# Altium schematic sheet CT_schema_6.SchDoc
size 260 x 245 mm
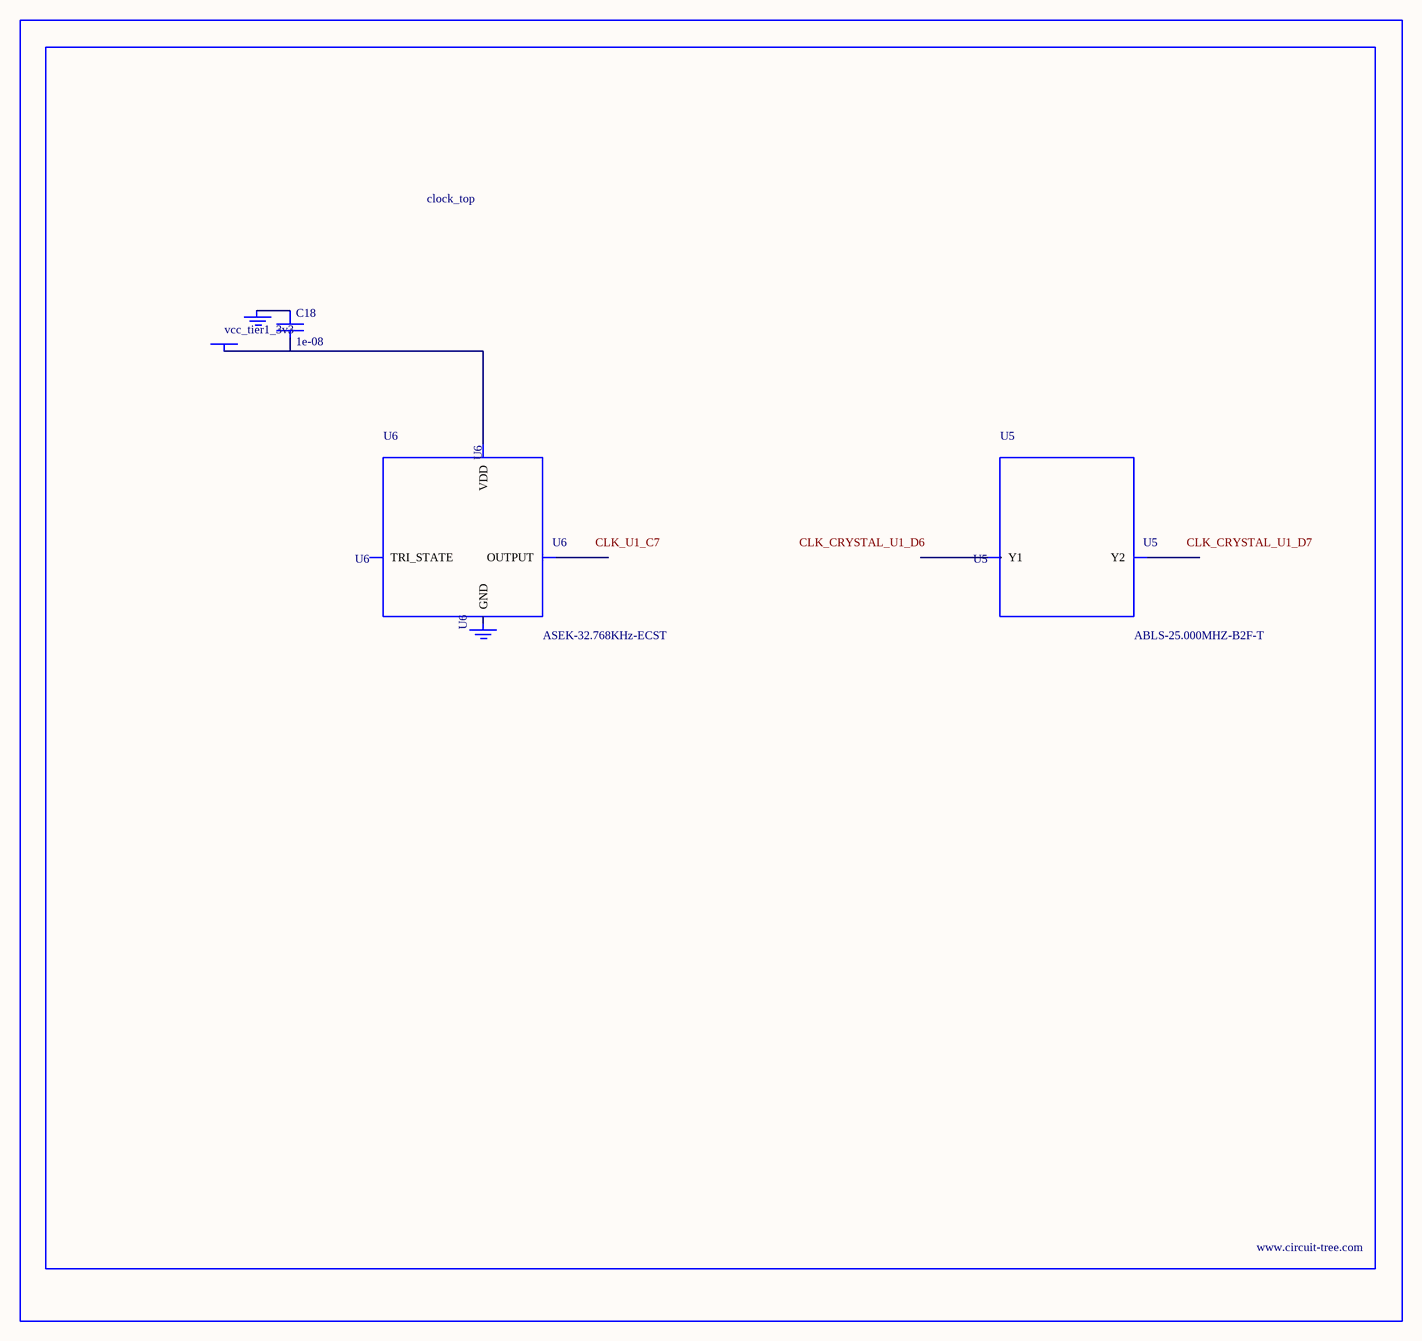
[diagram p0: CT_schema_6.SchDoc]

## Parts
BORDER5  (no value)
C18  1e-08  [C0402]
GND_INSTANCE_5_0  (no value)
GND_INSTANCE_5_1  (no value)
POWER_INSTANCE_5_0  vcc_tier1_3v3
U5  ABLS-25.000MHZ-B2F-T  [ABLS-25.000MHZ-B2F-T]
U6  ASEK-32.768KHz-ECST  [ASEK]

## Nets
NetC18_1: C18.1 GND_INSTANCE_5_0.0(GND)
NetC18_2: C18.2 POWER_INSTANCE_5_0.0(PWR) U6.4(VDD)

Not connected (* = marked no-connect by the designer): GND_INSTANCE_5_1 0(GND); U5 1(Y1) 2(Y2); U6 1(TRI_STATE) 2(GND) 3(OUTPUT)

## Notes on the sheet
- Labels drawn without touching a wire or pin: CLK_CRYSTAL_U1_D6, CLK_CRYSTAL_U1_D7, CLK_U1_C7

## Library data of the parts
BORDER5 = BORDER_PAGE5
C18 = C0402C103K3RAC
GND_INSTANCE_5_0 GND_INSTANCE_5_1 = GND
POWER_INSTANCE_5_0 = PWR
